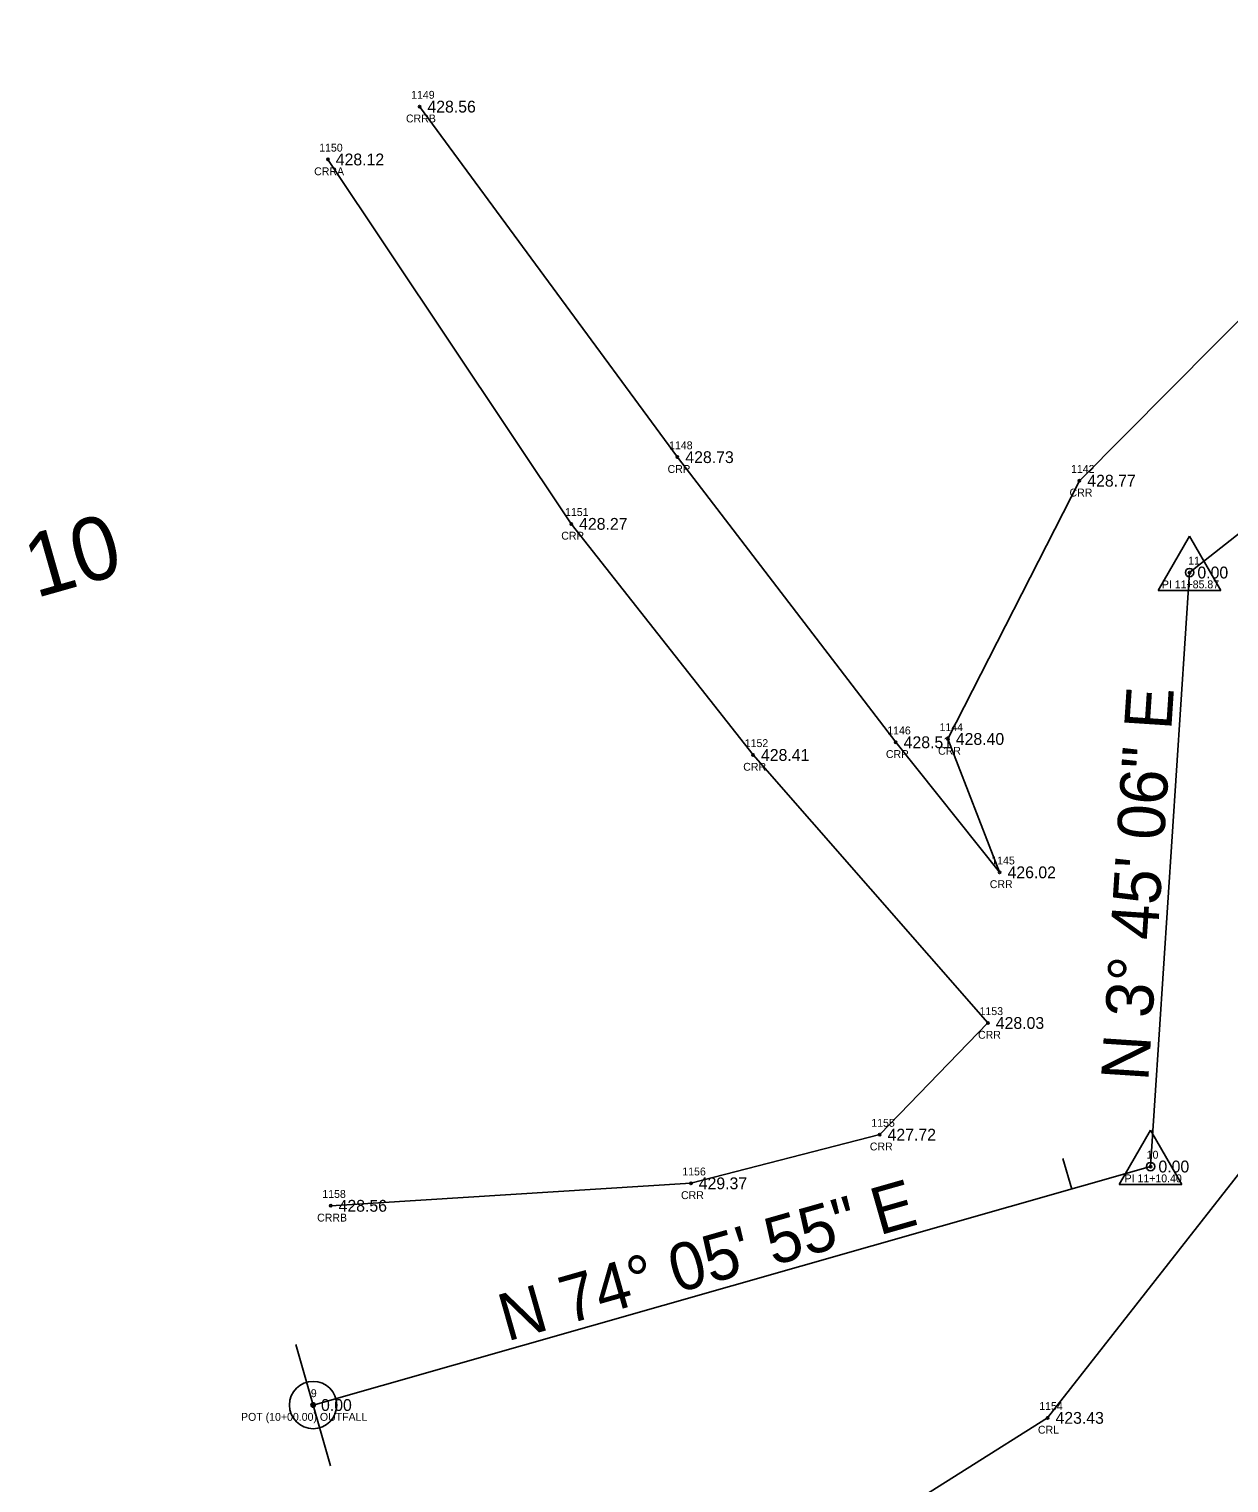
# Model space of a CAD drawing. Extents: x 1858454 to 1858924, y 1147053 to 1148170.
# Drawn here: x 1858454.3 to 1858606.4, y 1147434.7 to 1147619.1 of the extents above; entities that cross this region are included whole.
import ezdxf

# ---------------------------------------------------------------- set-up
doc = ezdxf.new("R2010")
doc.units = 0
for name, color, linetype in [('RD_EX_H2O', 7, 'Continuous'), ('RD_EX_H2O_txCode', 7, 'Continuous'), ('RD_EX_TX_H2O_ELEV', 7, 'Continuous'), ('RD_HC_Cl', 7, 'Continuous'), ('RD_HC_Data', 7, 'Continuous'), ('RD_HC_Data_Tic', 7, 'Continuous'), ('RD_HC_Survey_ELEV', 7, 'Continuous'), ('RD_HC_TX_Sta50', 7, 'Continuous'), ('RD_HC_txCode', 7, 'Continuous'), ('RD_SMD_Locator', 7, 'Continuous')]:
    doc.layers.add(name, color=color, linetype=linetype)

msp = doc.modelspace()

# ---------------------------------------------------------------- linework, layer by layer
at = {"layer": 'RD_EX_H2O'}
for points in [[(1858879.83, 1148102.54), (1858871.42, 1148034.27), (1858866.93, 1147971.73), (1858863.21, 1147909.44), (1858860.9, 1147860.04), (1858873.82, 1147825.54), (1858891.79, 1147781.55), (1858894.95, 1147773.07), (1858887.01, 1147735.25), (1858825.08, 1147733.03), (1858791.14, 1147702.41), (1858765.02, 1147654.77), (1858740.99, 1147628.76), (1858706.35, 1147596.83), (1858671.87, 1147580.02), (1858637.61, 1147560.56), (1858613.46, 1147539.88), (1858609.2, 1147499), (1858608.26, 1147474.71), (1858583.43, 1147442.99), (1858542.68, 1147417.32), (1858497.34, 1147430.55)], [(1858842, 1147848.22), (1858847.52, 1147794.04), (1858841.16, 1147786.48), (1858816.23, 1147769.28), (1858759.58, 1147742.8), (1858751.47, 1147732.35), (1858731.2, 1147689.66), (1858724.77, 1147677.64), (1858718.76, 1147662.14), (1858713.87, 1147646.5), (1858696.23, 1147629.99), (1858681.73, 1147631.9), (1858663.61, 1147613.98), (1858627.73, 1147602.37), (1858587.46, 1147561.81), (1858570.79, 1147529.07), (1858577.35, 1147512.16), (1858564.18, 1147528.65), (1858536.5, 1147564.8), (1858503.8, 1147609.24)], [(1858492.18, 1147602.54), (1858523.03, 1147556.34), (1858546.09, 1147527.04), (1858575.86, 1147493.06), (1858562.14, 1147478.9), (1858538.2, 1147472.73), (1858492.54, 1147469.88)]]:
    msp.add_lwpolyline(points, dxfattribs=at)
at = {"layer": 'RD_HC_Cl'}
for p, q in [((1858601.42, 1147550.17), (1858683.96, 1147615.39)), ((1858596.48, 1147474.86), (1858601.42, 1147550.17)), ((1858490.31, 1147444.62), (1858596.48, 1147474.86))]:
    msp.add_line(p, q, dxfattribs=at)
at = {"layer": 'RD_HC_Data'}
for p, q in [((1858597.45, 1147547.88), (1858601.42, 1147554.76)), ((1858601.42, 1147554.76), (1858605.39, 1147547.88)), ((1858597.45, 1147547.88), (1858605.39, 1147547.88)), ((1858592.51, 1147472.57), (1858596.48, 1147479.45)), ((1858596.48, 1147479.45), (1858600.45, 1147472.57)), ((1858592.51, 1147472.57), (1858600.45, 1147472.57))]:
    msp.add_line(p, q, dxfattribs=at)
for centre, radius in [((1858601.42, 1147550.17), 0.529), ((1858596.48, 1147474.86), 0.529), ((1858490.31, 1147444.62), 3), ((1858490.31, 1147444.62), 0.282)]:
    msp.add_circle(centre, radius, dxfattribs=at)
at = {"layer": 'RD_HC_Data_Tic'}
for p, q in [((1858586.48, 1147472.01), (1858585.38, 1147475.86)), ((1858490.31, 1147444.62), (1858488.12, 1147452.31)), ((1858490.31, 1147444.62), (1858492.5, 1147436.92))]:
    msp.add_line(p, q, dxfattribs=at)
at = {"layer": 'RD_SMD_Locator'}
for centre in [(1858503.8, 1147609.24), (1858492.18, 1147602.54), (1858536.5, 1147564.8), (1858587.46, 1147561.81), (1858523.03, 1147556.34), (1858601.42, 1147550.17), (1858570.79, 1147529.07), (1858564.18, 1147528.65), (1858546.09, 1147527.04), (1858577.35, 1147512.16), (1858575.86, 1147493.06), (1858562.14, 1147478.9), (1858596.48, 1147474.86), (1858538.2, 1147472.73), (1858492.54, 1147469.88), (1858490.31, 1147444.62), (1858583.43, 1147442.99)]:
    msp.add_circle(centre, 0.15, dxfattribs=at)

# ---------------------------------------------------------------- texts
at = {"layer": 'RD_EX_H2O_txCode'}
for s, p in [('1149', (1858502.74, 1147610.24)), ('CRRB', (1858502.08, 1147607.24)), ('1150', (1858491.08, 1147603.54)), ('CRRA', (1858490.44, 1147600.54)), ('1148', (1858535.44, 1147565.8)), ('CRR', (1858535.25, 1147562.8)), ('1142', (1858586.4, 1147562.81)), ('CRR', (1858586.21, 1147559.81)), ('1151', (1858522.25, 1147557.34)), ('CRR', (1858521.77, 1147554.34)), ('1144', (1858569.73, 1147530.07)), ('1152', (1858545.03, 1147528.04)), ('1146', (1858563.1, 1147529.65)), ('CRR', (1858562.93, 1147526.65)), ('CRR', (1858569.54, 1147527.07)), ('CRR', (1858544.84, 1147525.04)), ('1145', (1858576.29, 1147513.16)), ('CRR', (1858576.1, 1147510.16)), ('1153', (1858574.8, 1147494.06)), ('CRR', (1858574.61, 1147491.06)), ('1155', (1858561.08, 1147479.9)), ('CRR', (1858560.89, 1147476.9)), ('1156', (1858537.12, 1147473.73)), ('1158', (1858491.48, 1147470.88)), ('CRR', (1858536.95, 1147470.73)), ('CRRB', (1858490.82, 1147467.88)), ('1154', (1858582.37, 1147443.99)), ('CRL', (1858582.2, 1147440.99))]:
    msp.add_text(s, height=1, dxfattribs=at).set_placement(p)
at = {"layer": 'RD_EX_TX_H2O_ELEV'}
for s, p in [('428.56', (1858504.8, 1147608.49)), ('428.12', (1858493.18, 1147601.79)), ('428.73', (1858537.5, 1147564.05)), ('428.77', (1858588.46, 1147561.06)), ('428.27', (1858524.03, 1147555.59)), ('428.51', (1858565.18, 1147527.9)), ('428.40', (1858571.79, 1147528.32)), ('428.41', (1858547.09, 1147526.29)), ('426.02', (1858578.35, 1147511.41)), ('428.03', (1858576.86, 1147492.31)), ('427.72', (1858563.14, 1147478.15)), ('429.37', (1858539.2, 1147471.98)), ('428.56', (1858493.54, 1147469.13)), ('423.43', (1858584.43, 1147442.24))]:
    msp.add_text(s, height=1.5, dxfattribs=at).set_placement(p)
at = {"layer": 'RD_HC_Data'}
for s, rotation, p in [('N 3%%d 45\' 06" E', 86.2483, (1858596.18, 1147485.59)), ('N 74%%d 05\' 55" E', 15.9014, (1858514.88, 1147452.66))]:
    msp.add_text(s, height=6, rotation=rotation, dxfattribs=at).set_placement(p)
at = {"layer": 'RD_HC_Survey_ELEV'}
for p in [(1858602.42, 1147549.42), (1858597.48, 1147474.11), (1858491.31, 1147443.87)]:
    msp.add_text('0.00', height=1.5, dxfattribs=at).set_placement(p)
at = {"layer": 'RD_HC_TX_Sta50'}
msp.add_text('10', height=8, rotation=15.9014, dxfattribs=at).set_placement((1858455.14, 1147546.9))
at = {"layer": 'RD_HC_txCode'}
for s, p in [('11', (1858601.25, 1147551.17)), ('PI 11+85.87', (1858597.92, 1147548.17)), ('10', (1858595.99, 1147475.86)), ('PI 11+10.40', (1858593.19, 1147472.86)), ('9', (1858490.02, 1147445.62)), ('POT (10+00.00) OUTFALL', (1858481.17, 1147442.62))]:
    msp.add_text(s, height=1, dxfattribs=at).set_placement(p)

doc.saveas('drawing.dxf')
